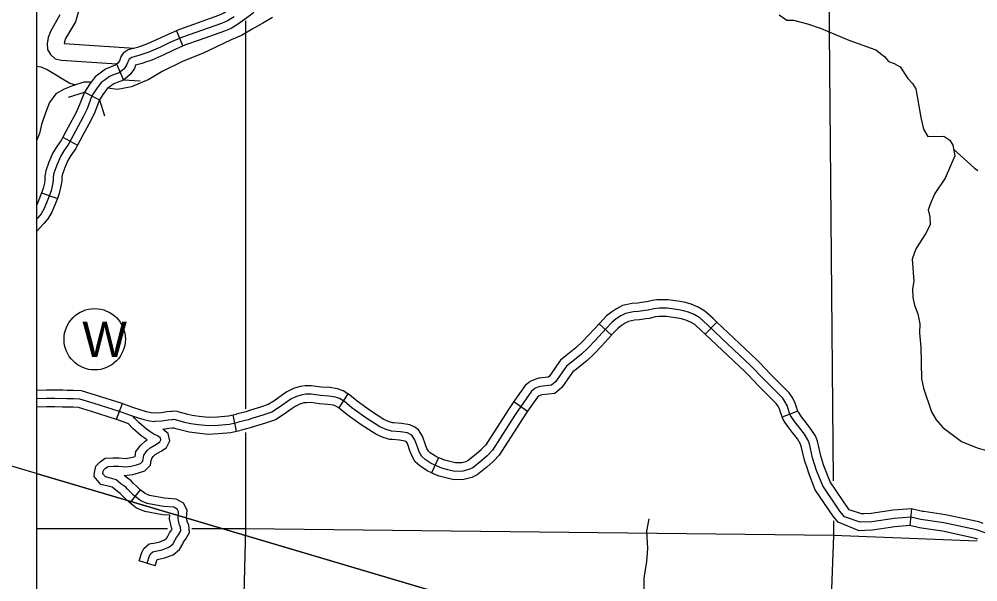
# Model space of a CAD drawing. Extents: x 0 to 3171, y 0 to 2059.
# Drawn here: x 1026.8 to 1170, y 855.9 to 939.9 of the extents above; entities that cross this region are included whole.
import ezdxf

# ---------------------------------------------------------------- set-up
doc = ezdxf.new("R2010")
doc.units = 0
for name, color, linetype in [('Default', 7, 'Continuous'), ('Level 32', 7, 'Continuous'), ('Level 35', 7, 'Continuous'), ('Level 38', 7, 'Continuous'), ('Level 45', 7, 'Continuous'), ('Level 46', 7, 'Continuous'), ('Level 5', 7, 'Continuous'), ('Level 57', 7, 'Continuous')]:
    doc.layers.add(name, color=color, linetype=linetype)

msp = doc.modelspace()

# ---------------------------------------------------------------- linework, layer by layer
at = {"layer": 'Default'}
msp.add_line((1029.42, 1254.61), (1029.42, 254.41), dxfattribs=at)
msp.add_lwpolyline([(2119.81, 1254.61), (1029.42, 1254.61), (1029.42, 254.41), (2119.81, 254.41)], close=True, dxfattribs=at)
msp.add_lwpolyline([(2119.81, 1254.61), (1029.42, 1254.61), (1029.42, 254.41), (2119.81, 254.41)], close=True, dxfattribs=at)
msp.add_lwpolyline([(2119.81, 1254.61), (1029.42, 1254.61), (1029.42, 254.41), (2119.81, 254.41)], close=True, dxfattribs=at)
for points in [[(641.57, 882.9), (992.89, 882.9), (1640.89, 690.88)], [(1029.42, 872.07), (1640.89, 690.88)]]:
    msp.add_lwpolyline(points, dxfattribs=at)
at = {"layer": 'Level 32'}
for p, q in [((1050.33, 938.12), (1051.3, 935.85)), ((1041.41, 933.18), (1042.42, 930.76)), ((1036.6, 928.97), (1038.83, 927.82)), ((1033.36, 922.24), (1035.56, 921.06)), ((1030.2, 913.96), (1032.55, 913.11))]:
    msp.add_line(p, q, dxfattribs=at)
for points in [[(1060.27, 942.78), (1059.83, 942.41), (1058.24, 941.23), (1057.4, 940.73), (1056.6, 940.4), (1052.88, 939.07)], [(1061.88, 940.87), (1061.38, 940.45), (1059.63, 939.15), (1058.52, 938.48), (1057.5, 938.07), (1053.72, 936.71)], [(1058.94, 940.19), (1057.96, 939.61), (1057.05, 939.23), (1051.25, 937.16), (1049.27, 936.3), (1047.97, 935.67), (1046.2, 934.92), (1044.87, 934.46), (1043.66, 934.13), (1043.28, 933.87), (1043.17, 933.69), (1042.94, 933.08), (1042.52, 932.45), (1041.8, 931.87), (1041.03, 931.59), (1040.35, 931.31), (1039.69, 930.82), (1039.12, 930.38)], [(1052.88, 939.07), (1050.79, 938.32), (1048.75, 937.43), (1047.45, 936.81), (1045.75, 936.09), (1044.75, 935.74)], [(1053.72, 936.71), (1051.71, 936), (1049.79, 935.16), (1048.48, 934.53), (1046.65, 933.75), (1045.58, 933.38)], [(1044.75, 935.74), (1044.5, 935.65), (1043.13, 935.28), (1042.36, 934.76), (1042.04, 934.25), (1041.82, 933.66), (1041.58, 933.3), (1041.17, 932.97), (1040.57, 932.75), (1039.73, 932.41), (1038.94, 931.82), (1038.22, 931.26), (1037.44, 930.24)], [(1045.58, 933.38), (1045.24, 933.26), (1044.24, 932.99), (1044.06, 932.5), (1043.45, 931.6), (1042.42, 930.76), (1041.48, 930.42), (1040.97, 930.21), (1040.44, 929.82), (1040.01, 929.49), (1039.42, 928.72)], [(1039.12, 930.38), (1038.42, 929.47), (1037.72, 928.4), (1036.98, 926.48), (1036.42, 925.27), (1035.25, 923.13), (1034.23, 921.22), (1033.53, 920.19), (1033.02, 919.35), (1032.46, 918.05), (1032.04, 916.88), (1031.95, 916.32), (1031.95, 915.81), (1031.85, 915.16), (1031.62, 914.22), (1031.15, 912.94), (1030.59, 911.59), (1030.13, 910.79), (1029.66, 910.23), (1029.42, 909.99)], [(1037.44, 930.24), (1037.4, 930.19), (1036.6, 928.97), (1035.83, 926.97), (1035.3, 925.83), (1034.15, 923.72), (1033.36, 922.24)], [(1039.44, 928.74), (1038.83, 927.82), (1038.13, 926), (1037.54, 924.71), (1036.35, 922.53), (1035.56, 921.06)], [(1033.36, 922.24), (1033.16, 921.87), (1032.48, 920.87), (1031.9, 919.93), (1031.29, 918.51), (1030.82, 917.2), (1030.7, 916.43), (1030.7, 915.9), (1030.62, 915.4), (1030.42, 914.59), (1030.2, 913.96)], [(1035.56, 921.06), (1035.3, 920.57), (1034.58, 919.51), (1034.13, 918.78), (1033.62, 917.59), (1033.25, 916.56), (1033.2, 916.22), (1033.2, 915.72), (1033.08, 914.92), (1032.82, 913.86), (1032.55, 913.11)], [(1030.2, 913.96), (1029.99, 913.39), (1029.47, 912.14), (1029.42, 912.06)], [(1032.55, 913.11), (1032.32, 912.49), (1031.72, 911.03), (1031.15, 910.07), (1030.59, 909.4), (1029.42, 908.19)]]:
    msp.add_lwpolyline(points, dxfattribs=at)
at = {"layer": 'Level 35'}
for points in [[(1064.68, 940.11), (1063.25, 939.28), (1061.65, 938.38), (1060.08, 937.42), (1058.52, 936.76), (1054.22, 934.75), (1051.36, 933.6), (1048.19, 932.04), (1046.23, 930.84), (1043.62, 929.76), (1041.54, 929.37), (1040.08, 929.57)], [(1140.38, 940.51), (1141.49, 939.72), (1142.49, 939.72), (1144.58, 939.15), (1146.66, 938.47), (1150.8, 936.71), (1154.81, 935.27), (1156.14, 934.24), (1156.72, 933.55), (1157.56, 933.26), (1158.42, 932.75), (1159.58, 930.99), (1160.31, 930.26), (1160.78, 929.48), (1161.52, 925.16), (1161.93, 923.46), (1162.56, 922.33), (1164.98, 922.4), (1165.84, 921.82), (1166.3, 921.07), (1166.61, 919.46), (1165.18, 916.11), (1163.6, 913.85), (1163.05, 912.58), (1162.62, 911.4), (1162.87, 910.35), (1162.94, 909.14), (1162.23, 907.81), (1160.76, 905.56), (1160.22, 904.05), (1160.47, 900.75), (1160.29, 899.61), (1160.33, 898.31), (1160.59, 897.18), (1161.1, 895.89), (1161.4, 894.39), (1161.31, 893.03), (1161.51, 890.9), (1161.62, 886.18), (1161.95, 884.8), (1163.13, 881.24), (1163.8, 880.05), (1164.8, 878.93), (1167.61, 876.82), (1169.96, 875.87), (1171.33, 875.49)], [(1029.42, 932.82), (1030.09, 932.73), (1031.05, 932.36), (1034.43, 930.28), (1035.25, 930.06)], [(1037.57, 930.45), (1036.49, 930.43), (1034.8, 929.93), (1033.58, 929.43), (1032.3, 928.69), (1031.38, 927.41), (1030.77, 925.86), (1030.19, 924.14), (1029.86, 922.78), (1029.42, 921.69)], [(1166.41, 920.47), (1169.55, 917.6), (1170.06, 917.27)], [(1120.91, 865.27), (1120.54, 863.43), (1120.7, 860.87), (1120.57, 858.93), (1120.17, 856.41), (1120.13, 854.26)]]:
    msp.add_lwpolyline(points, dxfattribs=at)
at = {"layer": 'Level 38'}
for points in [[(1040.82, 933.22), (1040.82, 933.22)], [(1044.91, 930.59), (1042.42, 930.76)], [(1034.22, 928.21), (1036.6, 928.97)], [(1038.83, 927.82), (1039.59, 925.44)]]:
    msp.add_lwpolyline(points, dxfattribs=at)
at = {"layer": 'Level 45'}
for p, q in [((1113.47, 894.39), (1115.31, 892.7)), ((1131.04, 894.64), (1129.33, 892.82)), ((1075.95, 883.92), (1074.58, 881.83)), ((1041.41, 880.15), (1042.28, 882.49)), ((1100.76, 882.78), (1102.8, 881.35)), ((1059.32, 878.36), (1058.83, 880.81)), ((1143.15, 881.37), (1140.83, 880.44)), ((1089.48, 874.41), (1088.46, 872.13)), ((1044.94, 869.63), (1043.38, 867.68)), ((1160.12, 866.8), (1159.91, 864.28)), ((1047.16, 858.28), (1044.78, 859.03))]:
    msp.add_line(p, q, dxfattribs=at)
for points in [[(1122.12, 897.95), (1121.4, 897.87), (1120.59, 897.66), (1120.16, 897.62), (1119.24, 897.49), (1118.42, 897.44), (1116.98, 897.12), (1116.07, 896.63), (1115.31, 896.13), (1114.6, 895.57), (1113.56, 894.49), (1113.47, 894.39)], [(1131.04, 894.64), (1130.49, 895.16), (1129.26, 896.28), (1128.25, 896.89), (1127.23, 897.31), (1126.38, 897.55), (1125.57, 897.71), (1123.72, 897.96), (1122.42, 897.99), (1122.12, 897.95)], [(1140.21, 883.97), (1139.25, 884.93), (1138.19, 886.01), (1136.11, 888.16), (1132.76, 891.32), (1129.64, 894.24), (1128.51, 895.28), (1127.69, 895.77), (1126.82, 896.12), (1126.09, 896.33), (1125.36, 896.48), (1123.62, 896.71), (1122.47, 896.73), (1121.63, 896.64), (1120.8, 896.43), (1120.31, 896.38), (1119.37, 896.24), (1118.59, 896.19), (1117.42, 895.93), (1116.71, 895.56), (1116.04, 895.11), (1115.44, 894.64), (1114.47, 893.63), (1112.89, 891.91), (1111.84, 890.81), (1110.85, 889.87), (1109.3, 888.62), (1108.62, 888.08), (1106.97, 885.73), (1106.36, 885.21), (1104.71, 885.05), (1104.31, 884.93), (1103.86, 884.72), (1103.37, 884.32), (1100.97, 880.91), (1097.54, 875.55), (1096.74, 874.7), (1095.94, 873.99), (1094.6, 872.91), (1094.01, 872.63), (1093.12, 872.4), (1091.9, 872.37), (1090.89, 872.61), (1089.99, 872.84), (1089.2, 873.17), (1088.41, 873.52), (1087.47, 874.16), (1087, 874.58), (1086.62, 875.26), (1086.39, 875.88), (1085.96, 877.08), (1085.56, 877.69), (1085.3, 877.88), (1084.83, 878.1), (1083.8, 878.27), (1082.44, 878.37), (1081.66, 878.6), (1080.72, 879.03), (1078.65, 880.34), (1076.56, 881.85), (1075.43, 882.77), (1074.68, 883.26), (1074.09, 883.45), (1073.08, 883.61), (1071.84, 883.71), (1070.45, 883.89), (1069.65, 883.87), (1069.11, 883.8), (1068.29, 883.54), (1067.44, 883.14), (1065.56, 881.83), (1064.58, 881.19), (1063.26, 880.77), (1061.77, 880.29), (1061.03, 880.06), (1059.57, 879.69)], [(1122.4, 895.47), (1121.85, 895.41), (1121.02, 895.19), (1120.46, 895.14), (1119.5, 895), (1118.77, 894.95), (1117.86, 894.75), (1117.36, 894.48), (1116.78, 894.1), (1116.28, 893.71), (1115.38, 892.77), (1115.31, 892.7)], [(1129.33, 892.82), (1128.79, 893.33), (1127.76, 894.27), (1127.13, 894.65), (1126.41, 894.94), (1125.8, 895.12), (1125.16, 895.24), (1123.53, 895.46), (1122.53, 895.48), (1122.4, 895.47)], [(1113.47, 894.39), (1111.98, 892.77), (1110.95, 891.69), (1110.02, 890.81), (1108.52, 889.6), (1107.7, 888.95), (1107.11, 888.11)], [(1137.47, 888.55), (1136.98, 889.05), (1133.61, 892.23), (1131.04, 894.64)], [(1115.31, 892.7), (1113.81, 891.06), (1112.72, 889.92), (1111.67, 888.93), (1110.08, 887.64), (1109.54, 887.21), (1109.16, 886.68)], [(1135.68, 886.81), (1135.23, 887.27), (1131.9, 890.41), (1129.33, 892.82)], [(1107.11, 888.11), (1106.04, 886.58), (1105.85, 886.42), (1104.47, 886.28), (1103.86, 886.1), (1103.19, 885.78), (1102.44, 885.18), (1100.76, 882.78)], [(1143.15, 881.37), (1143.11, 881.46), (1142.97, 881.94), (1142.71, 882.7), (1142.29, 883.44), (1141.88, 884.08), (1141.48, 884.49), (1141.09, 884.86), (1140.14, 885.81), (1139.09, 886.88), (1137.47, 888.55)], [(1109.16, 886.68), (1107.9, 884.88), (1106.87, 884.01), (1104.95, 883.81), (1104.75, 883.76), (1104.53, 883.65), (1104.29, 883.46), (1102.8, 881.35)], [(1140.83, 880.44), (1140.75, 880.64), (1140.59, 881.19), (1140.42, 881.68), (1140.16, 882.14), (1139.91, 882.51), (1139.72, 882.71), (1139.34, 883.07), (1138.36, 884.05), (1137.3, 885.14), (1135.68, 886.81)], [(1075.95, 883.92), (1075.23, 884.4), (1074.39, 884.67), (1073.23, 884.86), (1071.97, 884.95), (1070.52, 885.15), (1069.55, 885.12), (1068.84, 885.03), (1067.83, 884.71), (1066.81, 884.23), (1066.18, 883.78)], [(1029.42, 884.52), (1029.54, 884.51), (1030.91, 884.53), (1032.18, 884.53), (1033.36, 884.52)], [(1033.36, 884.52), (1034, 884.51), (1034.98, 884.51), (1036.1, 884.45), (1038.37, 883.73), (1042.18, 882.53), (1042.28, 882.49)], [(1066.18, 883.78), (1064.87, 882.86), (1064.04, 882.33), (1062.88, 881.96), (1061.39, 881.48), (1060.69, 881.26), (1059.26, 880.9)], [(1082.8, 879.6), (1082.66, 879.61), (1082.1, 879.78), (1081.32, 880.13), (1079.35, 881.38), (1077.32, 882.84), (1076.17, 883.78), (1075.95, 883.92)], [(1150.15, 865.56), (1149.44, 866.44), (1146.88, 870.2), (1145.96, 872.51), (1145.37, 874.37), (1144.88, 876.49), (1144.66, 877.09), (1144.13, 877.92), (1143.32, 878.99), (1142.71, 879.77), (1142.26, 880.43), (1142.07, 880.7), (1141.93, 881.05), (1141.78, 881.57), (1141.57, 882.19), (1141.23, 882.79), (1140.9, 883.3), (1140.6, 883.6), (1140.21, 883.97)], [(1029.42, 883.27), (1029.49, 883.26), (1030.92, 883.28), (1032.17, 883.28), (1033.99, 883.26), (1034.95, 883.26), (1035.88, 883.21), (1038, 882.54), (1041.77, 881.35), (1043.41, 880.74), (1044.64, 880.37), (1045.48, 880.11), (1046.34, 879.9), (1047.06, 879.83), (1047.09, 879.85), (1048.18, 879.9), (1049.09, 880.07), (1049.64, 880.12), (1049.76, 880.12), (1049.92, 880.15), (1050.15, 880.11), (1050.32, 880.06), (1051.52, 879.73), (1052.47, 879.52), (1053.58, 879.38), (1055.11, 879.19), (1056.54, 879.26), (1058.28, 879.43), (1059.57, 879.69)], [(1042.28, 882.49), (1043.8, 881.93), (1045, 881.57), (1045.81, 881.32), (1046.55, 881.14), (1047.02, 881.09), (1048.04, 881.15), (1048.91, 881.3), (1049.57, 881.37), (1049.67, 881.37), (1049.91, 881.41), (1050.44, 881.33), (1050.68, 881.25), (1050.71, 881.25)], [(1074.58, 881.83), (1074.14, 882.12), (1073.8, 882.23), (1072.94, 882.37), (1071.71, 882.46), (1070.39, 882.64), (1069.75, 882.62), (1069.38, 882.58), (1068.75, 882.38), (1068.07, 882.06), (1067.61, 881.73)], [(1100.76, 882.78), (1099.93, 881.6), (1096.55, 876.32), (1095.93, 875.66)], [(1029.42, 882.01), (1029.43, 882.01), (1030.93, 882.03), (1032.17, 882.03), (1033.33, 882.02)], [(1033.33, 882.02), (1033.98, 882.01), (1034.91, 882.01), (1035.65, 881.97), (1037.62, 881.35), (1041.36, 880.17), (1041.41, 880.15)], [(1050.71, 881.25), (1051.82, 880.95), (1052.69, 880.75), (1053.73, 880.62), (1055.15, 880.45), (1056.45, 880.51), (1058.1, 880.67), (1058.83, 880.81)], [(1058.83, 880.81), (1059.33, 880.91)], [(1067.61, 881.73), (1066.26, 880.79), (1065.12, 880.05), (1063.64, 879.58), (1062.14, 879.1), (1061.37, 878.86), (1059.88, 878.48)], [(1082.63, 877.1), (1082.21, 877.13), (1081.22, 877.43), (1080.13, 877.92), (1077.95, 879.31), (1075.8, 880.86), (1074.69, 881.76), (1074.58, 881.83)], [(1102.8, 881.35), (1102.01, 880.21), (1098.53, 874.77), (1097.75, 873.95)], [(1146.96, 873.5), (1146.57, 874.7), (1146.08, 876.85), (1145.78, 877.65), (1145.16, 878.63), (1144.31, 879.76), (1143.72, 880.51), (1143.29, 881.13), (1143.18, 881.29), (1143.15, 881.37)], [(1050.81, 864.38), (1050.77, 864.48), (1050.58, 865.36), (1050.65, 866.32), (1050.44, 866.72), (1049.93, 867.02), (1048.42, 867.13), (1045.97, 867.58), (1045.02, 867.97), (1043.99, 868.79), (1043.5, 869.26), (1043.04, 869.72), (1042.77, 870.02), (1042.04, 870.53), (1041.35, 871.11), (1040.67, 871.32), (1039.74, 871.53), (1039.34, 872), (1039.35, 872.04), (1039.44, 872.53), (1039.73, 872.82), (1040.13, 873.1), (1040.88, 873.15), (1041.69, 873.13), (1042.79, 873.03), (1043.58, 873.15), (1044.35, 873.36), (1044.98, 873.55), (1045.3, 873.87), (1045.35, 874.2), (1045.46, 874.8), (1045.95, 875.46), (1046.42, 875.88), (1047.37, 876.44), (1047.86, 876.76), (1048.03, 877.09), (1047.98, 877.32), (1047.61, 877.6), (1046.86, 877.95), (1045.86, 878.65), (1044.7, 879.65), (1044.09, 880.33), (1043.88, 880.61)], [(1041.41, 880.15), (1043.15, 879.5)], [(1045.96, 877.06), (1045.09, 877.66), (1043.82, 878.76), (1043.15, 879.5)], [(1089.48, 874.41), (1089.02, 874.62), (1088.24, 875.15), (1087.99, 875.37), (1087.76, 875.79), (1087.56, 876.31), (1087.09, 877.63), (1086.49, 878.56), (1085.93, 878.97), (1085.2, 879.3), (1083.95, 879.52), (1082.8, 879.6)], [(1144.58, 872.73), (1144.16, 874.04), (1143.68, 876.13), (1143.53, 876.53), (1143.1, 877.21), (1142.33, 878.23), (1141.7, 879.03), (1141.23, 879.72), (1140.96, 880.1), (1140.83, 880.44)], [(1042.55, 871.74), (1043.83, 871.92), (1044.69, 872.16), (1045.63, 872.44), (1046.48, 873.28), (1046.58, 873.99), (1046.64, 874.29), (1046.88, 874.61), (1047.16, 874.86), (1048.04, 875.38), (1048.83, 875.91), (1049.34, 876.91), (1049.11, 878.04), (1048.67, 878.37)], [(1048.29, 878.65), (1049.27, 878.83), (1049.7, 878.87), (1049.86, 878.87), (1049.89, 878.88), (1049.96, 878.86), (1050.06, 878.83)], [(1048.67, 878.37), (1048.29, 878.65)], [(1050.06, 878.83), (1051.22, 878.52), (1052.26, 878.29), (1053.42, 878.14), (1055.06, 877.94), (1056.63, 878.02), (1058.46, 878.19), (1059.32, 878.36)], [(1059.32, 878.36), (1059.82, 878.46)], [(1041.5, 874.38), (1041.76, 874.37), (1042.75, 874.29), (1043.32, 874.38), (1044, 874.56), (1044.15, 874.61), (1044.29, 875.32), (1045.03, 876.3), (1045.68, 876.89), (1045.96, 877.06)], [(1088.46, 872.13), (1087.8, 872.43), (1086.69, 873.17), (1086, 873.79), (1085.48, 874.74), (1085.21, 875.45), (1084.83, 876.52), (1084.64, 876.81), (1084.46, 876.89), (1083.65, 877.03), (1082.63, 877.1)], [(1095.93, 875.66), (1095.87, 875.6), (1095.13, 874.95), (1093.93, 873.98), (1093.58, 873.81), (1092.95, 873.64), (1092.03, 873.62), (1091.19, 873.82), (1090.39, 874.03), (1089.69, 874.32), (1089.48, 874.41)], [(1043.38, 867.68), (1043.17, 867.85), (1042.63, 868.36), (1042.13, 868.86), (1041.93, 869.08), (1041.28, 869.54), (1040.74, 870), (1040.35, 870.12), (1039.06, 870.41), (1038.06, 871.58), (1038.11, 872.2), (1038.28, 873.14), (1038.93, 873.78), (1039.7, 874.33), (1040.85, 874.4), (1041.5, 874.38)], [(1097.75, 873.95), (1097.61, 873.8), (1096.75, 873.04), (1095.27, 871.85), (1094.45, 871.45), (1093.29, 871.15), (1091.77, 871.12), (1090.59, 871.39), (1089.6, 871.65), (1088.7, 872.02), (1088.46, 872.13)], [(1150.81, 866.65), (1147.99, 870.79), (1147.14, 872.93), (1146.96, 873.5)], [(1149.17, 864.78), (1148.44, 865.69), (1145.77, 869.61), (1144.79, 872.09), (1144.58, 872.73)], [(1044.94, 869.63), (1044.81, 869.73), (1044.38, 870.15), (1043.94, 870.58), (1043.6, 870.96), (1042.81, 871.52), (1042.55, 871.74)], [(1051.94, 864.97), (1051.84, 865.45), (1051.92, 866.58), (1051.39, 867.61), (1050.32, 868.24), (1048.58, 868.38), (1046.33, 868.78), (1045.66, 869.06), (1044.94, 869.63)], [(1049.5, 864.45), (1049.32, 865.28), (1049.36, 865.81), (1048.26, 865.89), (1045.62, 866.37), (1044.38, 866.89), (1043.38, 867.68)], [(1153.07, 866.04), (1152.66, 866.03), (1150.81, 866.65)], [(1161.99, 866.36), (1161.79, 866.38), (1160.12, 866.8), (1157.38, 866.59), (1154.09, 866.08), (1153.07, 866.04)], [(1170.84, 864.6), (1170.17, 864.83), (1165.19, 865.9), (1161.99, 866.36)], [(1047.16, 858.28), (1047.46, 859.22), (1047.7, 859.27), (1048.58, 859.45), (1049.84, 859.93), (1050.78, 860.69), (1051.27, 861.55), (1051.41, 861.85), (1051.71, 862.21), (1052.28, 863.23), (1052.18, 864.34), (1051.96, 864.87), (1051.94, 864.97)], [(1193.56, 865.69), (1190.01, 862.93), (1186.83, 860.61), (1184.09, 859.58), (1181.51, 858.81), (1179.62, 858.64), (1178.25, 859.41), (1177.13, 860.44), (1175.5, 861.47), (1172.72, 862.65), (1169.83, 863.62), (1164.97, 864.67), (1161.55, 865.16), (1160.02, 865.54), (1157.53, 865.35), (1154.21, 864.84), (1152.48, 864.77), (1150.15, 865.56)], [(1044.78, 859.03), (1045.16, 860.26), (1045.49, 860.87), (1046.27, 861.54), (1047.22, 861.72), (1047.87, 861.86), (1048.58, 862.13), (1048.85, 862.35), (1049.05, 862.7), (1049.28, 863.2), (1049.64, 863.63), (1049.72, 863.76), (1049.67, 863.88), (1049.57, 864.08), (1049.5, 864.45)], [(1045.97, 858.65), (1046.32, 859.77), (1046.48, 860.07), (1046.83, 860.38), (1047.46, 860.49), (1048.23, 860.66), (1049.21, 861.03), (1049.81, 861.52), (1050.16, 862.13), (1050.35, 862.52), (1050.67, 862.92), (1051, 863.5), (1050.95, 864.04), (1050.81, 864.38)], [(1153.16, 863.55), (1152.3, 863.51), (1149.17, 864.78)], [(1161.64, 863.88), (1161.31, 863.93), (1159.91, 864.28), (1157.67, 864.1), (1154.32, 863.59), (1153.16, 863.55)], [(1170.04, 862.23), (1169.5, 862.41), (1164.75, 863.44), (1161.64, 863.88)]]:
    msp.add_lwpolyline(points, dxfattribs=at)
at = {"layer": 'Level 46'}
for points in [[(1029.42, 963.84), (1031.48, 964.61), (1032.32, 962.39), (1033.77, 960.21), (1034.24, 959.27), (1034.46, 958.39), (1034.37, 956.85), (1033.98, 955.71), (1033.39, 954.42), (1032.83, 953.06), (1032.64, 951.58), (1032.68, 950.66), (1032.75, 950.04), (1032.79, 949.27), (1033.62, 947.06), (1034.17, 945.78), (1035.23, 943.73), (1035.56, 942.5), (1035.67, 940.85), (1035.25, 939.46), (1033.79, 936.96), (1033.61, 936.48), (1033.57, 936.21), (1044.01, 935.52)], [(1032.94, 940.48), (1031.51, 938.03), (1031.18, 937.1), (1031.03, 936.16), (1031.08, 935.31), (1031.54, 934.57), (1032.24, 933.93), (1033.16, 933.73), (1041.43, 933.18)]]:
    msp.add_lwpolyline(points, dxfattribs=at)
at = {"layer": 'Level 5'}
for points in [[(1147.76, 949.24), (1148.43, 870.96)], [(1060.65, 939.62), (1060.67, 881.7)], [(1060.67, 878.17), (1060.67, 863.81)], [(1148.48, 864.98), (1148.5, 862.8)], [(1049, 863.8), (1029.42, 863.78)], [(1060.67, 863.81), (1052.65, 863.8)], [(1060.67, 863.81), (1060.35, 852.02), (1057.97, 785.97)], [(1148.5, 862.8), (1060.67, 863.81)], [(1148.5, 862.8), (1145.79, 790.93)], [(1169.95, 861.97), (1148.5, 862.8)]]:
    msp.add_lwpolyline(points, dxfattribs=at)
at = {"layer": 'Level 57'}
msp.add_circle((1038.13, 892.08), 4.58, dxfattribs=at)

# ---------------------------------------------------------------- texts
msp.add_text('W', height=5.28, dxfattribs=at).set_placement((1036.28, 889.44))

doc.saveas('drawing.dxf')
